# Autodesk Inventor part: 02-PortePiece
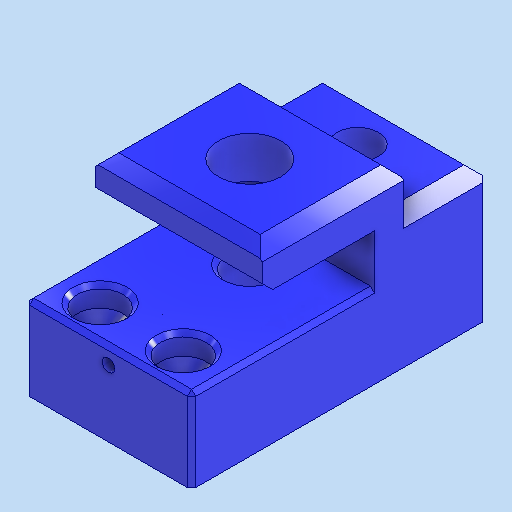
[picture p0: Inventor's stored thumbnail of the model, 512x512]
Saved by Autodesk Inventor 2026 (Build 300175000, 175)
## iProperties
Created: 2025-12
Part Number: 02-PortePiece
Material: Générique
Document SubType Name: Modeling
Designer: thierry.jost
Density: 1 g/cm^3
Appearance: Bleu - Peinture murale - Brillant
Author: thierry.jost
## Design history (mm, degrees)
sketch "Esquisse1"
  geometry: L1 (4.338, 31.619)-(4.338, -39.381); L2 (4.338, -39.381)-(36.338, -39.381); L3 (36.338, -39.381)-(36.338, -19.381); L4 (36.338, -19.381)-(46.338, -19.381); L5 (46.338, -19.381)-(46.338, 14.619); L6 (46.338, 14.619)-(36.338, 14.619); L7 (36.338, 14.619)-(36.338, -12.381); L8 (36.338, -12.381)-(24.338, -12.381); L9 (24.338, -12.381)-(24.338, 31.619); L10 (24.338, 31.619)-(4.338, 31.619); 1 further point
  constraints: 20 end point, 8 perpendicular, 2 point on line, 1 vertical
  dimensions: "d0" = 71 distance of L1.start L1.end; "d1" = 44 distance of L8.end L9.end; "d2" = 20 distance of L2.end L3.end; "d3" = 34 distance of L4.end L5.end; "d4" = 27 distance of L6.end L7.end (derived); "d5" = 20 distance of L9.end L1.start; "d6" = 32 distance of L1.end L2.end; "d7" = 10 distance of L3.end L4.end
extrude "Extrusion1" new body sketch "Esquisse1" distance "d8" = 40; taper "d9" = 0 deg
sketch "Esquisse2"
  geometry: L1 (0, 0)-(40, 0) reference; L2 (40, 34)-(40, 0) reference; 2 further points
  dimensions: "d17" = 17 distance from line of L1 point (20, 17); "d18" = 20 distance from line of L2 point (20, 17)
hole "Perçage1" sketch "Esquisse2" at (20, 17) diameter "d10" = 15; stored, may be unused: countersink angle "d14" = 90 deg, drill point angle "d16" = 118 deg; dims "d11" = 6, "d12" = 4, "d13" = 2, "d15" = 10
sketch "Esquisse3"
  geometry: L1 (40, 44)-(40, 0) reference; C1 r 7.5 at (20, 34) reference; 3 further points
  constraints: 1 midpoint
  dimensions: "d26" = 20 horizontal distance of point (40, 22) point (20, 34); "d27" = 0 distance of C1.centre point (20, 34)
hole "Perçage2" sketch "Esquisse3" at (20, 34) diameter "d19" = 11; stored, may be unused: countersink angle "d23" = 90 deg, drill point angle "d25" = 118 deg; dims "d20" = 6, "d21" = 4, "d22" = 2, "d24" = 10
sketch "Esquisse4"
  geometry: L1 (0, 44)-(0, 0) reference; C1 r 5.5 at (20, 34) reference; 2 further points
  dimensions: "d35" = 10 distance from line of point (10, 8) L1; "d61" = 26 vertical distance of point (10, 8) C1.centre
hole "Perçage3" sketch "Esquisse4" at (10, 8) diameter "d28" = 11; stored, may be unused: countersink angle "d32" = 90 deg, drill point angle "d34" = 118 deg; dims "d29" = 6, "d30" = 4, "d31" = 2, "d33" = 5
sketch "Esquisse5"
  geometry: L1 (0, 20)-(0, 0) reference; L2 (0, 20)-(40, 20) reference; 2 further points
  dimensions: "d44" = 20 distance from line of L1 point (20, 16); "d45" = 4 distance from line of L2 point (20, 16)
hole "Perçage4" sketch "Esquisse5" at (20, 16) diameter "d37" = 3; stored, may be unused: countersink angle "d41" = 90 deg, drill point angle "d43" = 118 deg; dims "d38" = 6, "d39" = 4, "d40" = 2, "d42" = 6
sketch "Esquisse6"
  geometry: L1 (40, 20)-(40, 0) reference; L2 (0, 20)-(40, 20) reference; 2 further points
  dimensions: "d53" = 20 distance from line of L1 point (20, 9); "d54" = 11 distance from line of L2 point (20, 9)
hole "Perçage5" sketch "Esquisse6" at (20, 9) diameter "d46" = 10; stored, may be unused: countersink angle "d50" = 90 deg, drill point angle "d52" = 118 deg; dims "d47" = 6, "d48" = 4, "d49" = 2, "d51" = 6
chamfer "Chanfrein1" distance "d55" = 2.5; stored, may be unused: second distance "d56" = 2, angle "d57" = 45 deg
chamfer "Chanfrein2" distance "d58" = 3; stored, may be unused: second distance "d59" = 2, angle "d60" = 45 deg
node "Plan de construction1"
mirror "Mise en miroir1"
chamfer "Chanfrein3" distance "d63" = 1; stored, may be unused: second distance "d64" = 2, angle "d65" = 45 deg
sketch "Esquisse7"
  geometry: L1 (0, 69)-(0, 0) reference; L2 (1, 70)-(39, 70) reference; 2 further points
  dimensions: "d73" = 20 distance from line of L1 point (20, 57); "d74" = 13 distance from line of point (20, 57) L2
hole "Perçage6" sketch "Esquisse7" at (20, 57) diameter "d66" = 8.376; stored, may be unused: countersink angle "d70" = 90 deg, drill point angle "d72" = 118 deg; dims "d67" = 16, "d68" = 4, "d69" = 2, "d71" = 17.5
chamfer "Chanfrein4" distance "d75" = 1; stored, may be unused: second distance "d76" = 2, angle "d77" = 45 deg
node "Solide1"
